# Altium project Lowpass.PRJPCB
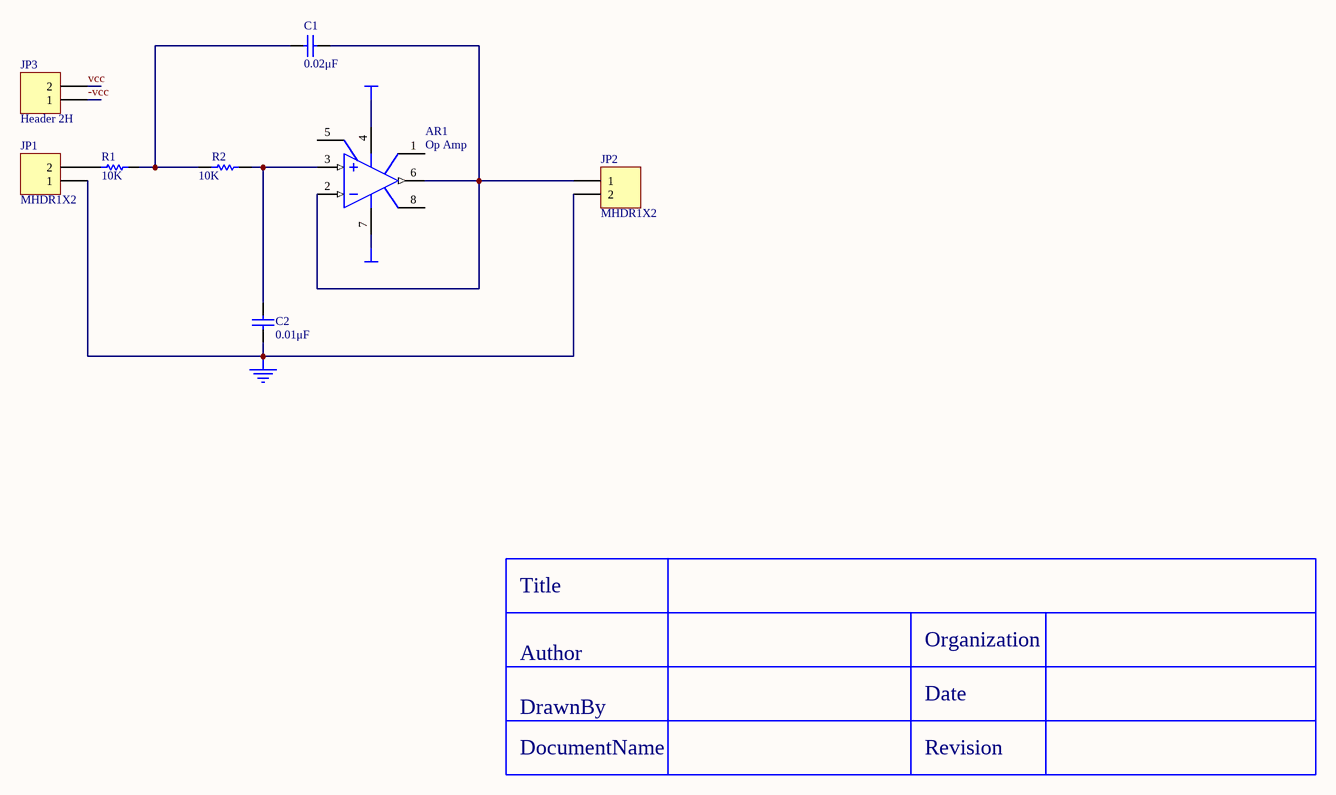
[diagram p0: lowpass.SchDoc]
1 sheet, 8 parts. Net scope: global (net labels, ports and power ports of the same name join across sheets).
Board file: Lowpass.PCBDOC

## Sheet lowpass.SchDoc: LowPass
size B; Date: 4,20,2004; Author: Yangzd; DrawnBy: Yangzd; Organization: scu edu; Revision: 1.0

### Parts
AR1  Op Amp  [CAN-8/D9.4]
C1  0.02μF  [C3216-1206]
C2  value 0.01μF  [C3216-1206]  (hidden comment: Cap Semi)
JP1  MHDR1X2  [MHDR1X2]
JP2  MHDR1X2  [MHDR1X2]
JP3  Header 2H  [HDR1X2H]
R1  value 10K  [AXIAL-0.3]  (hidden comment: Res1)
R2  value 10K  [AXIAL-0.3]  (hidden comment: Res1)

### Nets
-vcc: AR1.7(V+) JP3.1
GND: C2.1 JP1.1 JP2.2
vcc: AR1.4(V-) JP3.2
NetAR1_2: AR1.2(IN-) AR1.6(OUT) C1.2 JP2.1
NetAR1_3: AR1.3(IN+) C2.2 R2.2
NetC1_1: C1.1 R1.2 R2.1
NetJP1_2: JP1.2 R1.1

Not connected (* = marked no-connect by the designer): AR1 1(OS_NUL) 5(OS_NUL) 8(TAB)

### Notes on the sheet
- Title
- Author
- Organization
- DocumentName
- DrawnBy
- Revision
- Date

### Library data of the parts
AR1 = Op Amp: FET Operational Amplifier; Manufacturer: Generic Components
C1 C2 = Cap Semi: Capacitor (Semiconductor SIM Model); Manufacturer: Generic Components; Class I: Passive
JP1 JP2 = MHDR1X2: Header, 2-Pin; Manufacturer: Generic Components; Class I: Connector
JP3 = Header 2H: Header, 2-Pin,  Right Angle; Manufacturer: Generic Components; Class I: Connector
R1 R2 = Res1: Resistor; Manufacturer: Generic Components; Class I: Passive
